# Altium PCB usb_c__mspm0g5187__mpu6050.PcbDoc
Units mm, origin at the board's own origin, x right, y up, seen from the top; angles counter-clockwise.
Board outline 64 x 33 mm, 2 copper layers (Top, Bottom), stack 0 mm thick; 29 components, 21 nets, 180 pads, 72 vias.
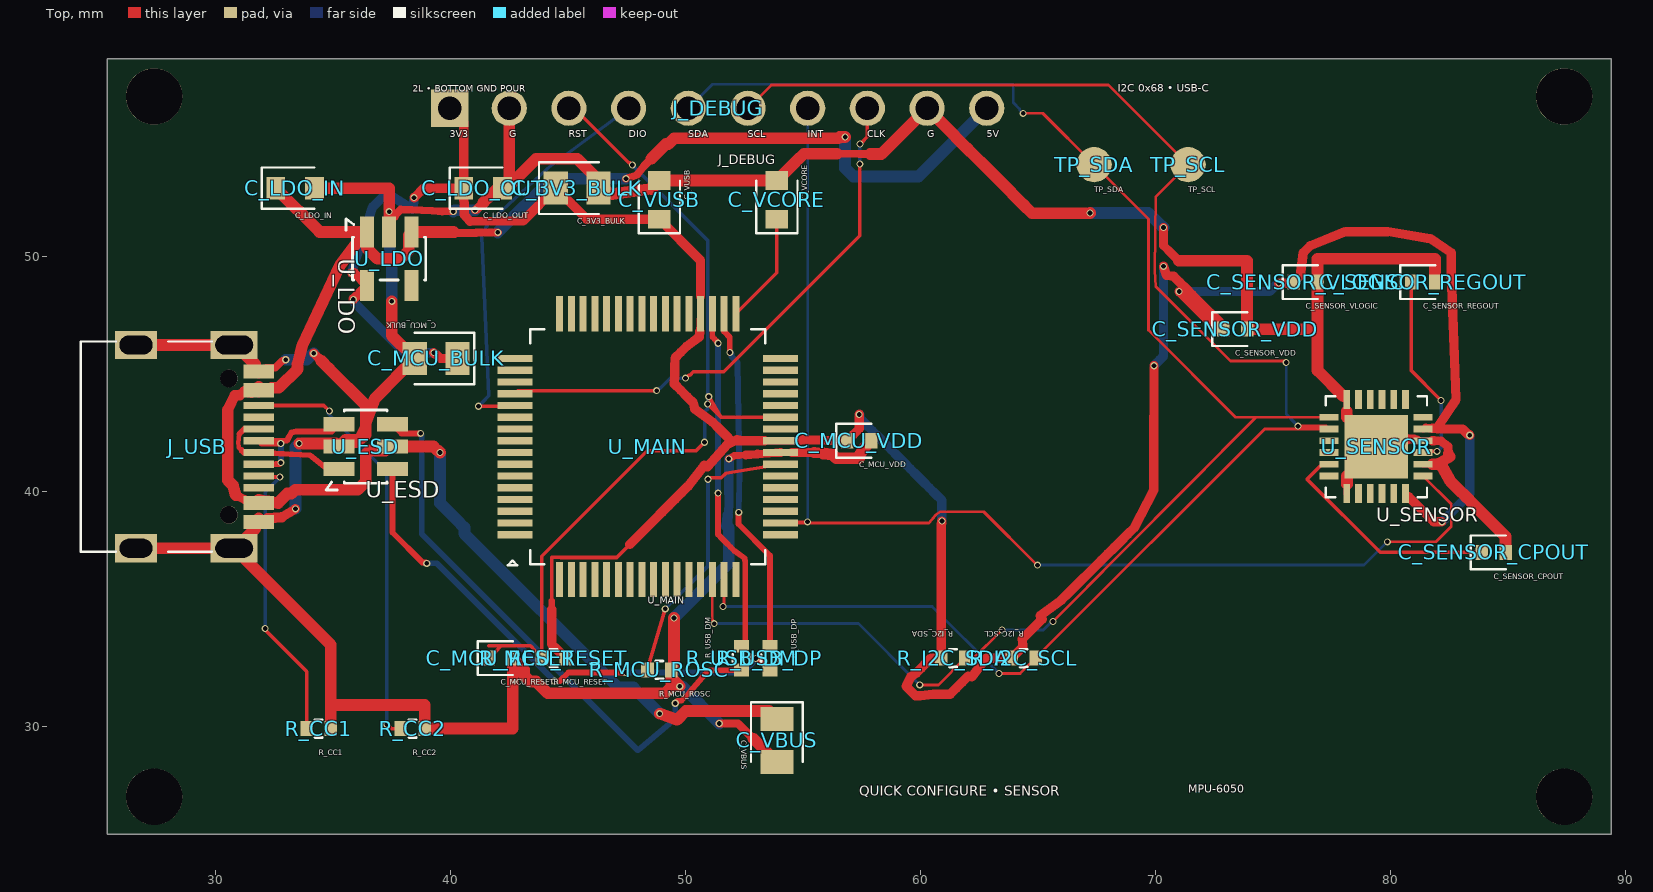
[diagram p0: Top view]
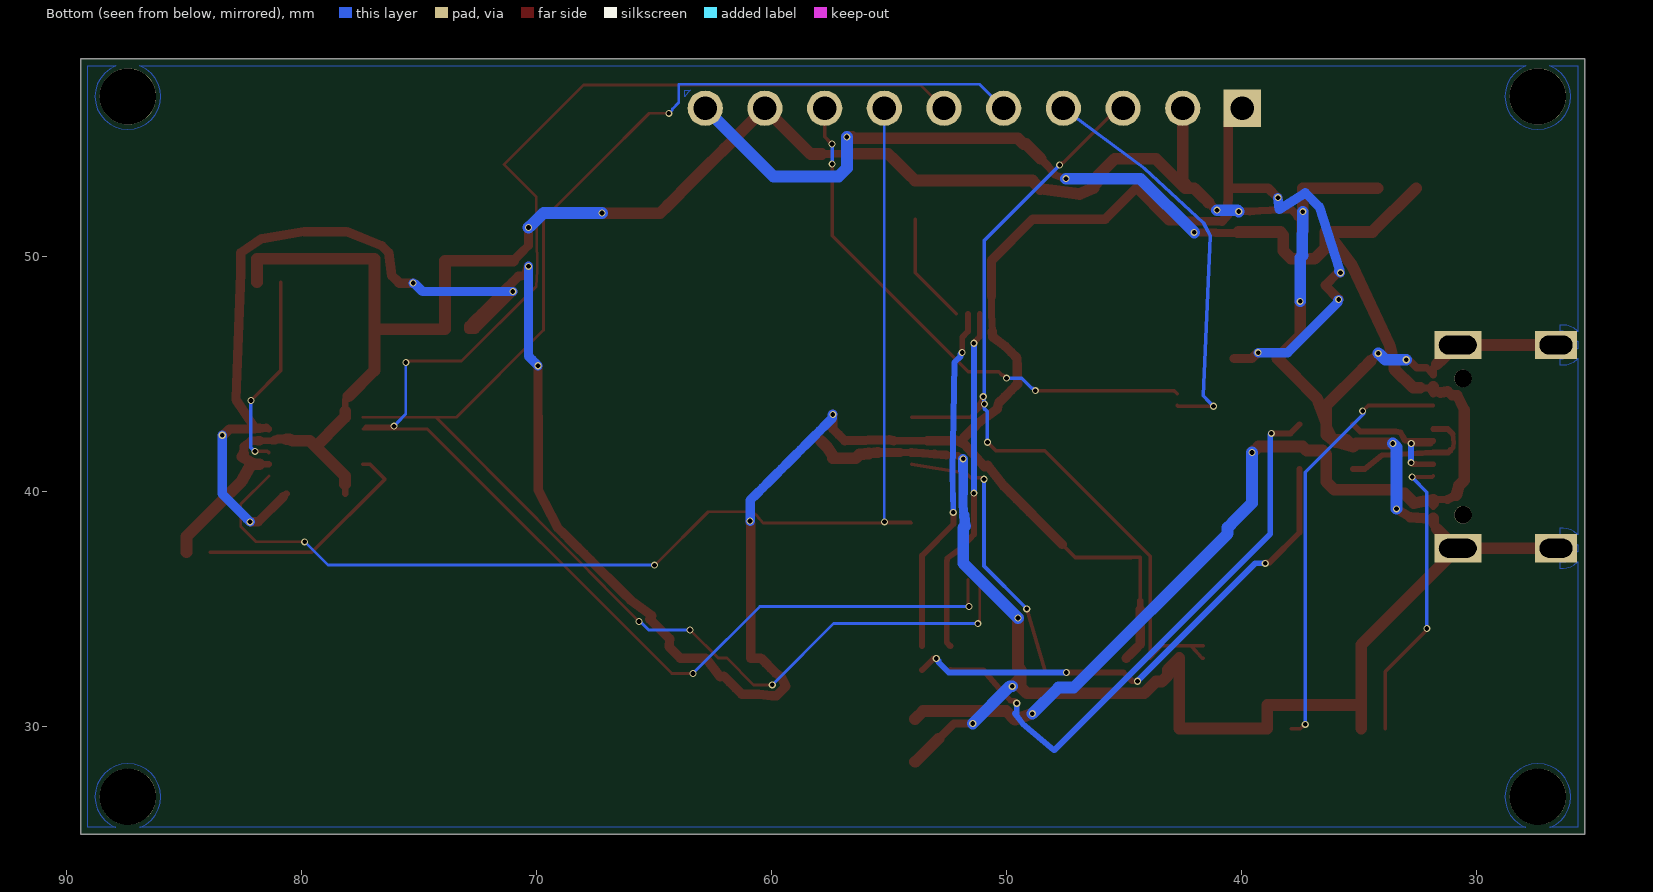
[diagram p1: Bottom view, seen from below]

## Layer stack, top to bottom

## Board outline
25.4,58.4 89.4,58.4 89.4,25.4 25.4,25.4

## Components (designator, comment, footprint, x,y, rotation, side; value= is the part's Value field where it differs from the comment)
C_3V3_BULK "" TSCIRCUIT-2.8500x1.4000mm 45.4,52.9 r0 top
C_LDO_IN "" TSCIRCUIT-2.4500x0.9500mm 33.4,52.9 r0 top
C_LDO_OUT "" TSCIRCUIT-2.4500x0.9500mm 41.4,52.9 r0 top
C_MCU_BULK "" TSCIRCUIT-2.8500x1.4000mm 39.4,45.65 r180 top
C_MCU_RESET "" TSCIRCUIT-1.5600x0.6400mm 42.15,32.9 r0 top
C_MCU_VDD "" TSCIRCUIT-1.5600x0.6400mm 57.4,42.15 r0 top
C_SENSOR_CPOUT "" TSCIRCUIT-1.5600x0.6400mm 84.4,37.4 r0 top
C_SENSOR_REGOUT "" TSCIRCUIT-1.5600x0.6400mm 81.4,48.9 r0 top
C_SENSOR_VDD "" TSCIRCUIT-1.5600x0.6400mm 73.4,46.9 r0 top
C_SENSOR_VLOGIC "" TSCIRCUIT-1.5600x0.6400mm 76.4,48.9 r0 top
C_VBUS "" TSCIRCUIT-1.4000x2.8500mm 53.9,29.4 r270 top
C_VCORE "" TSCIRCUIT-0.9500x2.4500mm 53.9,52.4 r90 top
C_VUSB "" TSCIRCUIT-0.9500x2.4500mm 48.9,52.4 r90 top
J_DEBUG "" TSCIRCUIT-24.3600x1.5000mm 51.4,56.3 r0 top
J_USB "" TSCIRCUIT-6.7732x9.8502mm 29.112,41.9 r90 top
R_CC1 "" TSCIRCUIT-1.5600x0.6400mm 34.4,29.9 r0 top
R_CC2 "" TSCIRCUIT-1.5600x0.6400mm 38.4,29.9 r0 top
R_I2C_SCL "" TSCIRCUIT-1.5600x0.6400mm 64.4,32.9 r180 top
R_I2C_SDA "" TSCIRCUIT-1.5600x0.6400mm 61.4,32.9 r180 top
R_MCU_RESET "" TSCIRCUIT-1.5600x0.6400mm 44.4,32.9 r0 top
R_MCU_ROSC "" TSCIRCUIT-1.5600x0.6400mm 48.9,32.4 r0 top
R_USB_DM "" TSCIRCUIT-0.6400x1.5600mm 52.4,32.9 r90 top
R_USB_DP "" TSCIRCUIT-0.6400x1.5600mm 53.6,32.9 r90 top
TP_SCL "" TSCIRCUIT-1.5000x1.5000mm 71.4,53.9 r0 top
TP_SDA "" TSCIRCUIT-1.5000x1.5000mm 67.4,53.9 r0 top
U_ESD "" TSCIRCUIT-3.6000x2.5000mm 36.4,41.9 r0 top
U_LDO "" TSCIRCUIT-2.5000x3.6000mm 37.4,49.9 r270 top
U_MAIN "" TSCIRCUIT-12.8000x12.8000mm 48.4,41.9 r0 top
U_SENSOR "" TSCIRCUIT-4.8000x4.8000mm 79.4,41.9 r0 top

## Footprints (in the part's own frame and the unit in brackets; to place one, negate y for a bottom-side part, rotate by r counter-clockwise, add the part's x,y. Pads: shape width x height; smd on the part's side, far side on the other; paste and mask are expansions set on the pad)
TSCIRCUIT-0.6400x1.5600mm [mm]
  rect 0.54x0.64 smd: 1(-0.51,0) 2(0.51,0)
  silkscreen extent -0.15,-0.38 0.15,0.38
TSCIRCUIT-0.9500x2.4500mm [mm]
  rect 0.8x0.95 smd: 1(-0.825,0) 2(0.825,0)
  silkscreen extent -1.42,-0.88 0.82,0.87
TSCIRCUIT-1.4000x2.8500mm [mm]
  rect 1.025x1.4 smd: 1(-0.913,0) 2(0.913,0)
  silkscreen extent -1.63,-1.1 0.91,1.1
TSCIRCUIT-1.5000x1.5000mm [mm]
  round 1.5 smd: 1(0,0)
TSCIRCUIT-1.5600x0.6400mm [mm]
  rect 0.54x0.64 smd: 1(-0.51,0) 2(0.51,0)
  silkscreen extent -0.98,-0.72 0.51,0.72
TSCIRCUIT-2.4500x0.9500mm [mm]
  rect 0.8x0.95 smd: 1(-0.825,0) 2(0.825,0)
  silkscreen extent -1.42,-0.88 0.82,0.87
TSCIRCUIT-2.5000x3.6000mm [mm]
  rect 1.325x0.6 smd: 1(-1.138,-0.95) 2(-1.138,0) 3(-1.138,0.95) 4(1.137,0.95) 5(1.137,-0.95)
  silkscreen extent -1.69,-1.84 0.91,1.56
TSCIRCUIT-2.8500x1.4000mm [mm]
  rect 1.025x1.4 smd: 1(-0.913,0) 2(0.913,0)
  silkscreen extent -1.63,-1.1 0.91,1.1
TSCIRCUIT-3.6000x2.5000mm [mm]
  rect 1.325x0.6 smd: 1(-1.138,-0.95) 2(-1.138,0) 3(-1.138,0.95) 4(1.137,0.95) 5(1.137,0) 6(1.137,-0.95)
  silkscreen extent -1.69,-1.84 0.91,1.56
TSCIRCUIT-4.8000x4.8000mm [mm]
  rect 0.28x0.8 smd: 1(-1.25,2) 2(-0.75,2) 3(-0.25,2) 4(0.25,2) 5(0.75,2) 6(1.25,2) 13(1.25,-2) 14(0.75,-2) 15(0.25,-2) 16(-0.25,-2) 17(-0.75,-2) 18(-1.242,-2)
  rect 0.8x0.28 smd: 7(2,1.25) 8(2,0.75) 9(2,0.25) 10(2,-0.25) 11(2,-0.75) 12(2,-1.25) 19(-2,-1.25) 20(-2,-0.75) 21(-2,-0.25) 22(-2,0.25) 23(-2,0.75) 24(-2,1.25)
  rect 2.7x2.7 smd: 25(0.012,0)
  silkscreen extent -2.14,-2.15 2.16,2.15
TSCIRCUIT-6.7732x9.8502mm [mm]
  rect 0.3x1.3 smd: 1(-3.35,-2.737) 2(-3.05,-2.737) 3(-2.55,-2.737) 4(-2.25,-2.737) 5(-1.75,-2.737) 6(-1.25,-2.737) 7(-0.75,-2.737) 8(-0.25,-2.737) 9(0.25,-2.737) 10(0.75,-2.737) 11(1.25,-2.737) 12(1.75,-2.737) 13(2.55,-2.737) 14(2.25,-2.737) 15(3.35,-2.737) 16(3.05,-2.737)
  rect 1.2x2 hole 0.8 slot 1.6 at 90 deg: 17(-4.325,-1.693) 18(4.325,-1.693)
  rect 1.2x1.8 hole 0.8 slot 1.4 at 90 deg: 19(4.325,2.487) 20(-4.325,2.487)
  round 0.75 hole 0.75 unplated: NPTH-1(-2.9,-1.468) NPTH-2(2.9,-1.468)
  silkscreen extent -4.47,-0.75 4.47,4.83
TSCIRCUIT-12.8000x12.8000mm [mm]
  rect 1.5x0.3 smd: 1(-5.65,-3.75) 2(-5.65,-3.25) 3(-5.65,-2.75) 4(-5.65,-2.25) 5(-5.65,-1.75) 6(-5.65,-1.25) 7(-5.65,-0.75) 8(-5.65,-0.25) 9(-5.65,0.25) 10(-5.65,0.75) 11(-5.65,1.25) 12(-5.65,1.75) 13(-5.65,2.25) 14(-5.65,2.75) 15(-5.65,3.25) 16(-5.65,3.75) 33(5.65,3.75) 34(5.65,3.25) 35(5.65,2.75) 36(5.65,2.25) 37(5.65,1.75) 38(5.65,1.25) 39(5.65,0.75) 40(5.65,0.25) 41(5.65,-0.25) 42(5.65,-0.75) 43(5.65,-1.25) 44(5.65,-1.75) 45(5.65,-2.25) 46(5.65,-2.75) 47(5.65,-3.25) 48(5.65,-3.75)
  rect 0.3x1.5 smd: 17(-3.75,5.65) 18(-3.25,5.65) 19(-2.75,5.65) 20(-2.25,5.65) 21(-1.75,5.65) 22(-1.25,5.65) 23(-0.75,5.65) 24(-0.25,5.65) 25(0.25,5.65) 26(0.75,5.65) 27(1.25,5.65) 28(1.75,5.65) 29(2.25,5.65) 30(2.75,5.65) 31(3.25,5.65) 32(3.75,5.65) 49(3.75,-5.65) 50(3.25,-5.65) 51(2.75,-5.65) 52(2.25,-5.65) 53(1.75,-5.65) 54(1.25,-5.65) 55(0.75,-5.65) 56(0.25,-5.65) 57(-0.25,-5.65) 58(-0.75,-5.65) 59(-1.25,-5.65) 60(-1.75,-5.65) 61(-2.25,-5.65) 62(-2.75,-5.65) 63(-3.25,-5.65) 64(-3.75,-5.65)
  silkscreen extent -5.95,-5.05 5,5
TSCIRCUIT-24.3600x1.5000mm [mm]
  rect 1.6x1.6 hole 1: 1(-11.43,0)
  round 1.5 hole 1: 2(-8.89,0) 3(-6.35,0) 4(-3.81,0) 5(-1.27,0) 6(1.27,0) 7(3.81,0) 8(6.35,0) 9(8.89,0) 10(11.43,0)

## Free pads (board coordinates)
  round 2.4 hole 2.4 unplated: NPTH-3(27.4,27) NPTH-4(87.4,27) NPTH-5(27.4,56.8) NPTH-6(87.4,56.8)

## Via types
v1: diameter 0.3, hole 0.2, Top to Bottom, 72 vias

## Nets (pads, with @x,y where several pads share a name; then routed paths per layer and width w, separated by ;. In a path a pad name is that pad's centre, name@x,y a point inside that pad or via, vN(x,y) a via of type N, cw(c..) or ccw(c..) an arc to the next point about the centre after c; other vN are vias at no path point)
".J_DEBUG > .pin4 to .U_MAIN > .pin12": J_DEBUG.4 U_MAIN.12 | length 17.3
  Top w0.15: v1(41.2,43.617) 42.717,43.617 U_MAIN.12
  Bottom w0.15: v1(41.2,43.617) 41.374,43.791 41.64,44.057 41.33,50.856 41.64,51.43 44.119,53.725 J_DEBUG.4
".J_DEBUG > .pin8 to .U_MAIN > .pin13": J_DEBUG.8 U_MAIN.13 | length 23
  Top w0.15: U_MAIN.13 42.88,44.28 v1(48.782,44.28) ; v1(50.011,44.814) 50.139,44.942 50.2,44.942 50.338,45.08 51.641,45.08 57.43,50.869 v1(57.43,53.93) ; v1(57.434,54.775) 57.546,54.857 57.546,54.884 57.75,55.088 J_DEBUG.8
  Bottom w0.15: v1(48.782,44.28) 48.892,44.39 48.94,44.39 49.364,44.814 v1(50.011,44.814) ; v1(57.43,53.93) 57.447,53.947 57.447,54.002 57.434,54.015 v1(57.434,54.775)
".U_MAIN > .pin42 to .R_MCU_ROSC > .pin1": R_MCU_ROSC.1 U_MAIN.42 | length 12.2
  Top w0.15: R_MCU_ROSC.1 v1(49.149,34.998) ; v1(50.968,40.512) 51.029,40.573 51.54,40.573 51.735,40.762 U_MAIN.42
  Bottom w0.15: v1(49.149,34.998) 49.177,35.026 50.968,36.817 v1(50.968,40.512)
GND: C_3V3_BULK.2 C_LDO_IN.2 C_LDO_OUT.2 C_MCU_BULK.2 C_MCU_RESET.2 C_MCU_VDD.2 C_SENSOR_CPOUT.2 C_SENSOR_REGOUT.2 C_SENSOR_VDD.2 C_SENSOR_VLOGIC.2 C_VBUS.2 C_VCORE.2 C_VUSB.2 J_DEBUG.2 J_DEBUG.9 J_USB.1 J_USB.2 J_USB.15 J_USB.16 J_USB.17 J_USB.18 J_USB.19 J_USB.20 R_CC1.2 R_CC2.2 R_MCU_ROSC.2 U_ESD.2 U_LDO.2 U_MAIN.41 U_SENSOR.1 U_SENSOR.9 U_SENSOR.11 U_SENSOR.18 U_SENSOR.25 | length 180.9
  Top w0.275: J_USB.16 J_USB.15@32.153,45.254
  Top w0.28: U_SENSOR.1@78.01,44.04 U_SENSOR.1 78.15,43.775 78.15,43.65 78.15,43.525 78.15,43.5 78.15,43.4 ; U_SENSOR.18 78.158,40.025 78.158,40.15 78.158,40.275 78.158,40.3 ; U_SENSOR.9@81,42.219 U_SENSOR.9@81.025,42.219 ; U_SENSOR.9@81.251,42.143 U_SENSOR.9 ; U_SENSOR.11 81.494,41.15 81.587,41.15 81.681,41.15 81.775,41.15 81.8,41.15 U_SENSOR.11 ; U_SENSOR.9 81.588,42.15 81.681,42.15 81.775,42.15 U_SENSOR.9@81.8,42.15
  Top w0.3: J_USB.1@31.699,38.4 J_USB.1 J_USB.1@31.849,38.7 ; 31.699,45.4 J_USB.15 J_USB.16@31.849,45.1 ; J_USB.2 31.945,38.839 32.037,38.85 32.13,38.85 J_USB.2@32.224,38.85 ; U_MAIN.41 U_MAIN.41@54.53,41.65
  Top w0.31: J_USB.16 J_USB.16@31.849,45.1
  Top w0.312: v1(51.857,41.378) 52.088,41.509 52.578,41.545
  Top w0.318: U_SENSOR.9@81.133,42.184 U_SENSOR.9@81.251,42.143
  Top w0.325: J_USB.15@32.153,45.254 32.542,45.254 32.847,45.559 v1(32.999,45.596) ; 37.883,51.98 38.356,51.98 38.791,51.955 39.226,51.931 39.661,51.907 v1(40.126,51.909) ; v1(41.055,51.962) v1@41.082,51.982 ; v1(51.447,30.117) 51.844,30.118 52.24,30.119 ; 56.46,54.36 56.929,54.358 57.398,54.355 57.868,54.353
  Top w0.35: 37.614,51.711 37.883,51.98 ; 52.24,30.119 52.572,29.793 52.904,29.467
  Top w0.375: v1@41.082,51.982 41.105,51.982 41.411,52.288 ; 52.578,41.545 53.069,41.58 53.559,41.615 U_MAIN.41 ; U_MAIN.41@54.53,41.65 55.01,41.65 55.49,41.65 ; v1(70.351,51.227) 70.351,50.843 70.351,50.459 70.675,50.135 70.998,49.812 ; 80.775,42.219 80.9,42.219 81,42.219 ; U_SENSOR.9@81.025,42.219 U_SENSOR.9@81.133,42.184 ; 81.869,42.15 81.963,42.15 82.056,42.15 82.105,42.15 82.155,42.136 82.462,41.9 82.475,41.588
  Top w0.4: 32.838,38.9 33.124,39.075 v1(33.411,39.251) ; v1(34.191,45.872) 34.516,45.547 ; U_LDO.2@37.426,51.524 37.614,51.711 ; U_SENSOR.25@80.65,42.219 80.775,42.219
  Top w0.413: 81.8,42.15 81.869,42.15
  Top w0.45: J_USB.2@32.224,38.85 32.531,38.875 32.838,38.9 ; 55.49,41.65 55.877,41.608 ; 82.013,41.15 82.044,41.181 82.3,41.322 82.556,41.463 82.475,41.588
  Top w0.5: J_USB.20 J_USB.17 ; J_USB.19 J_USB.18 ; J_USB.18 30.874,46.225 31.474,45.625 31.699,45.4 ; J_USB.1@31.699,38.4 31.474,38.175 30.874,37.575 J_USB.17 34.91,33.471 R_CC1.2 34.91,30.9 38.91,30.9 R_CC2.2 42.66,29.9 C_MCU_RESET.2 42.66,32.89 43.15,32.4 43.15,32.15 43.4,31.9 43.65,31.9 44.15,31.4 49.141,31.4 49.41,31.669 R_MCU_ROSC.2 ; J_USB.1@31.849,38.7 J_USB.2 ; v1(33.571,42.037) 35.126,42.037 U_ESD.2 ; C_LDO_IN.2 37.4,52.9 U_LDO.2 ; 34.516,45.547 34.84,45.223 36.4,43.663 36.4,42.7 36.2,42.3 36,42.1 U_ESD.2 ; v1(37.4,51.9) 37.401,51.036 U_LDO.2 ; U_LDO.2@37.426,51.524 37.426,51.064 U_LDO.2 ; v1(37.513,48.083) 37.513,46.624 C_MCU_BULK.2 38.151,45.313 37.814,44.976 37.477,44.639 37.14,44.303 36.803,43.966 36.4,42.9 36.4,42.4 36.129,42.184 35.546,42.184 U_ESD.2 ; 41.411,52.288 41.717,52.594 42.023,52.9 C_LDO_OUT.2 ; J_DEBUG.2 42.51,53.185 C_LDO_OUT.2 ; v1(49.517,34.603) 49.517,34.184 49.517,33.765 49.517,33.345 49.517,32.926 49.517,32.507 R_MCU_ROSC.2 ; v1(49.766,31.699) 49.41,32.055 R_MCU_ROSC.2 ; 52.904,29.467 53.883,28.487 C_VBUS.2 ; 55.877,41.608 56.263,41.567 56.43,41.4 57.4,41.4 57.4,41.525 57.66,41.9 C_MCU_VDD.2 ; 56.46,54.36 55.99,54.362 55.521,54.365 55.052,54.367 54.764,54.081 54.476,53.796 54.188,53.51 C_VCORE.2 C_VUSB.2 48.9,53.193 48.575,52.868 46.9,52.65 C_3V3_BULK.2 46.4,52.9 46.15,53.15 46.15,53.4 45.4,54.15 43.65,54.15 42.4,52.9 C_LDO_OUT.2 ; 57.868,54.353 58.337,54.351 58.341,54.351 J_DEBUG.9 60.634,55.956 60.977,55.613 61.321,55.269 61.664,54.926 62.008,54.582 62.351,54.239 62.695,53.895 63.038,53.552 63.382,53.208 63.725,52.865 64.069,52.521 64.412,52.178 64.756,51.834 65.242,51.834 65.729,51.834 66.216,51.834 66.703,51.834 67.19,51.834 67.219,51.834 v1(67.228,51.843) ; 70.998,49.812 73.91,49.812 C_SENSOR_VDD.2 76.91,46.9 C_SENSOR_VLOGIC.2 ; 78.01,44.04 76.91,45.14 C_SENSOR_VLOGIC.2 ; 78.15,43.4 78.15,43.275 78.15,43.162 78.159,43.154 78.247,43.065 78.336,42.977 U_SENSOR.25 ; 78.158,40.3 78.158,40.4 78.158,40.525 78.158,40.645 78.161,40.649 78.25,40.737 78.338,40.825 U_SENSOR.25 ; U_SENSOR.25@80.65,42.219 80.525,42.219 80.4,42.15 79.662,42.15 U_SENSOR.25 ; C_SENSOR_REGOUT.2 81.91,49.9 76.91,49.9 C_SENSOR_VLOGIC.2 ; 82.013,41.15 81.962,41.15 81.869,41.15 81.8,41.15 82.15,41.15 82.554,40.43 82.89,40.094 83.227,39.757 83.563,39.421 83.9,39.084 84.237,38.747 84.573,38.411 84.91,38.074 84.91,37.737 C_SENSOR_CPOUT.2
  Bottom w0.375: 51.816,38.971 51.856,39.416 51.857,39.907
  Bottom w0.4: 51.857,39.907 51.857,40.397 51.857,40.888
  Bottom w0.425: 51.857,40.888 v1(51.857,41.378)
  Bottom w0.45: 51.775,38.525 51.816,38.971
  Bottom w0.5: v1(32.999,45.596) 33.446,45.596 33.892,45.596 34.143,45.847 34.166,45.847 v1(34.191,45.872) ; v1(33.411,39.251) 33.411,41.877 v1(33.571,42.037) ; v1(37.4,51.9) 37.419,50.126 37.408,50.038 37.513,49.934 v1(37.513,48.083) ; v1(40.126,51.909) 40.18,51.962 v1(41.055,51.962) ; v1(49.517,34.603) 51.856,36.942 51.856,38.435 51.775,38.525 ; v1(49.766,31.699) 49.865,31.699 v1(51.447,30.117) ; v1(67.228,51.843) 67.723,51.843 68.218,51.843 68.713,51.843 69.208,51.843 69.703,51.843 69.976,51.57 70.25,51.296 70.282,51.296 v1(70.351,51.227)
MAIN_RESET: C_MCU_RESET.1 J_DEBUG.3 R_MCU_RESET.1 U_MAIN.38 | length 41.2
  Top w0.15: C_MCU_RESET.1 41.68,32.9 42.16,33.425 41.64,33.425 43.2,33.425 43.16,33.425 43.41,33.425 R_MCU_RESET.1 43.89,37.238 48.382,41.73 50.459,41.73 50.758,42.029 50.763,42.029 v1(50.82,42.086) ; J_DEBUG.3 45.273,56.3 47.59,53.983 47.65,53.983 v1(47.746,53.887) ; v1(50.951,43.713) 51.514,43.15 ; v1(51,44.025) 51.514,43.15 ; 51.514,43.15 U_MAIN.38 51.514,43.15
  Bottom w0.15: v1(47.746,53.887) 50.948,50.685 50.948,43.716 v1(50.951,43.713) ; v1(50.82,42.086) 50.82,43.378 50.966,43.524 50.966,43.698 v1(51,44.025)
MSP_VCORE: C_VCORE.1 U_MAIN.32 | length 4.7
  Top w0.15: U_MAIN.32 53.9,49.3 C_VCORE.1
SENSOR_CPOUT: C_SENSOR_CPOUT.1 U_SENSOR.20 | length 9.9
  Top w0.15: U_SENSOR.20 77.095,41.15 76.459,40.514 79.573,37.4 C_SENSOR_CPOUT.1
SENSOR_INT: J_DEBUG.7 U_MAIN.47 U_SENSOR.12 | length 51.9
  Top w0.12: v1(55.2,38.7) 54.1,38.7 U_MAIN.47 60.377,38.65 60.662,39 60.853,39.126 62.702,39.126 64.929,36.898 64.95,36.898 v1(64.992,36.856) ; v1(79.876,37.849) 81.941,37.849 82.601,38.508 82.601,39.45 U_SENSOR.12
  Bottom w0.12: v1(55.2,38.7) 55.198,38.698 55.124,38.698 55.21,38.784 J_DEBUG.7 ; v1(64.992,36.856) 78.883,36.856 79.841,37.814 v1(79.876,37.849)
SENSOR_REGOUT: C_SENSOR_REGOUT.1 U_SENSOR.10 | length 8.4
  Top w0.15: C_SENSOR_REGOUT.1 80.89,45.139 82.113,43.916 v1(82.165,43.864) ; U_SENSOR.10 81.464,41.706 v1(81.992,41.701)
  Bottom w0.15: v1(81.992,41.701) 82.076,41.741 82.076,41.773 82.165,41.863 v1(82.165,43.864)
SENSOR_SCL: J_DEBUG.6 R_I2C_SCL.1 TP_SCL.1 U_MAIN.50 U_SENSOR.23 | length 70
  Top w0.12: v1(51.607,35.099) 51.65,35.142 51.65,35.25 U_MAIN.50 ; J_DEBUG.6 53.663,57.293 68.007,57.293 TP_SCL.1 70.018,52.518 69.979,49.395 70.018,48.723 73.199,45.542 75.449,45.542 75.514,45.542 v1(75.573,45.483) ; v1(63.354,32.242) 64.252,32.242 R_I2C_SCL.1 74.66,42.65 U_SENSOR.23 77.278,42.772 v1(76.072,42.772)
  Bottom w0.12: v1(51.607,35.099) 60.507,35.099 63.243,32.363 63.243,32.353 v1(63.354,32.242) ; v1(75.573,45.483) 75.573,43.283 75.961,42.895 75.961,42.883 v1(76.072,42.772)
SENSOR_SDA: J_DEBUG.5 R_I2C_SDA.1 TP_SDA.1 U_MAIN.51 U_SENSOR.24 | length 70.7
  Top w0.12: U_MAIN.51 51.15,34.532 51.173,34.51 51.173,34.423 v1(51.229,34.367) ; v1(59.978,31.762) 60.772,31.762 R_I2C_SDA.1 62.276,32.9 63.431,34.055 v1(63.476,34.1) ; v1(64.379,56.084) 65.216,56.084 TP_SDA.1 69.707,51.593 69.707,46.856 73.412,43.15 U_SENSOR.24 74.286,43.15 v1(65.648,34.456)
  Bottom w0.12: J_DEBUG.5 51.153,57.323 63.956,57.323 63.956,56.54 64.231,56.265 64.231,56.232 v1(64.379,56.084) ; v1(51.229,34.367) 57.373,34.367 59.909,31.831 v1(59.978,31.762) ; v1(63.476,34.1) 65.236,34.1 65.581,34.445 v1(65.648,34.456)
usb-dm-mcu: R_USB_DM.2 U_MAIN.30 | length 14.8
  Top w0.25: U_MAIN.30 51.15,47.307 51.15,47.063 51.15,46.82 51.15,46.576 51.248,46.479 51.345,46.381 51.345,46.355 v1(51.4,46.3) ; v1(51.399,39.922) 51.399,39.701 51.399,39.481 51.399,39.26 51.399,39.039 51.399,38.819 51.399,38.598 51.399,38.377 51.399,38.157 51.574,37.982 51.748,37.807 51.923,37.632 52.098,37.458 52.525,37.15 52.556,37 52.556,36.757 52.556,36.513 52.556,36.27 52.556,36.027 52.556,35.784 52.556,35.54 52.556,35.297 52.556,35.054 52.556,34.811 52.556,34.567 52.556,34.324 52.556,34.081 52.556,33.838 52.556,33.594 52.556,33.566 R_USB_DM.2
  Bottom w0.25: v1(51.399,39.922) 51.403,39.926 51.403,40.052 51.4,40.055 51.4,40.305 51.4,40.555 51.4,40.805 51.4,41.054 51.4,41.304 51.4,41.554 51.4,41.804 51.4,42.054 51.4,42.303 51.4,42.553 51.4,42.803 51.4,43.053 51.4,43.302 51.4,43.552 51.4,43.802 51.4,44.052 51.4,44.302 51.4,44.551 51.4,44.801 51.4,45.051 51.4,45.301 51.4,45.551 51.4,45.8 51.4,46.05 v1(51.4,46.3)
usb-dm-phy: R_USB_DM.1 U_ESD.4 | length 24.9
  Top w0.25: U_ESD.4 37.922,42.466 v1(38.74,42.466) ; v1(49.574,30.98) 49.678,31.084 49.702,31.073 49.84,31.1 50.2,31.46 51,32.386 R_USB_DM.1
  Bottom w0.25: v1(38.74,42.466) 38.784,42.422 38.784,42.351 38.784,38.179 47.981,28.982 49.321,30.109 49.649,30.544 49.574,30.576 v1(49.574,30.98)
usb-dm-port: J_USB.7 J_USB.9 U_ESD.3 | length 6.5
  Top w0.25: J_USB.7 32.584,41.15 32.595,41.16 32.732,41.16 v1(32.789,41.217) ; v1(32.787,42.037) 31.965,42.034 J_USB.9 33.044,42.15 33.241,42.5 33.436,42.542 34.955,42.542 U_ESD.3
  Bottom w0.25: v1(32.787,42.037) 32.791,42.03 32.791,41.965 32.789,41.963 v1(32.789,41.217)
usb-dp-mcu: R_USB_DP.2 U_MAIN.31 | length 14.9
  Top w0.25: U_MAIN.31 U_MAIN.31 51.652,46.803 51.895,46.56 v1(51.895,45.902) ; v1(52.276,39.102) 52.264,39.063 52.264,38.607 53.6,37.271 R_USB_DP.2
  Bottom w0.25: v1(51.895,45.902) 51.962,45.835 51.962,45.742 52.229,45.478 52.307,40.802 v1(52.276,39.102)
usb-dp-phy: R_USB_DP.1 U_ESD.6 | length 22
  Top w0.25: U_ESD.6 37.537,38.245 38.807,36.976 38.959,36.976 v1(39,36.935) ; v1(44.437,31.916) 44.658,31.916 45.031,32.289 47.421,32.289 47.444,32.312 v1(47.466,32.29) ; v1(53,32.88) 53.11,32.88 R_USB_DP.1
  Bottom w0.25: v1(39,36.935) 39.423,36.935 44.426,31.932 44.426,31.927 v1(44.437,31.916) ; v1(47.466,32.29) 52.468,32.29 52.91,32.731 52.91,32.79 v1(53,32.88)
usb-dp-port: J_USB.8 J_USB.10 U_ESD.1 | length 6.1
  Top w0.188: 31.018,42.432 30.997,42.241 30.977,42.05 31.007,41.854 31.11,41.75
  Top w0.238: 31.018,42.432 31.126,42.541
  Top w0.25: 31.11,41.75 31.214,41.647 31.425,41.647 31.635,41.647 31.846,41.647 J_USB.8 34.036,41.531 34.764,40.952 35.261,40.952 U_ESD.1 ; 31.126,42.541 31.235,42.65 31.44,42.65 31.644,42.65 J_USB.10
USB_CC1: J_USB.6 R_CC1.1 | length 12.7
  Top w0.15: J_USB.6 31.892,40.607 v1(32.746,40.607) ; v1(32.121,34.156) 32.112,34.147 32.072,34.147 33.89,32.329 R_CC1.1
  Bottom w0.15: v1(32.121,34.156) 32.121,39.961 32.704,40.544 32.704,40.565 v1(32.746,40.607)
USB_CC2: J_USB.12 R_CC2.1 | length 18.2
  Top w0.15: J_USB.12 34.62,43.65 v1(34.851,43.419) ; v1(37.296,30.08) 37.394,29.982 37.424,29.982 37.506,29.9 R_CC2.1
  Bottom w0.15: v1(34.851,43.419) 34.81,43.378 34.81,43.299 37.296,40.813 v1(37.296,30.08)
VBUS5: C_LDO_IN.1 C_VBUS.1 J_DEBUG.10 J_USB.3 J_USB.4 J_USB.13 J_USB.14 U_ESD.5 U_LDO.1 U_LDO.3 | length 83.1
  Top w0.275: J_USB.3 J_USB.3@31.849,39.5
  Top w0.3: J_USB.4@31.244,39.65 31.546,39.65 J_USB.4 J_USB.3@31.849,39.5 ; J_USB.14@31.546,44.197 J_USB.14 J_USB.14@31.849,44.3 ; J_USB.13 32.1,44.4 J_USB.13@32.4,44.4
  Top w0.325: v1(47.481,53.303) 47.947,53.462 48.251,53.846
  Top w0.35: 40.181,50.99 40.642,50.997 41.103,51.003 41.564,51.01 v1(42.025,51.017) ; 48.251,53.846 48.559,54.154
  Top w0.375: 30.869,39.837 J_USB.4@31.244,39.65
  Top w0.437: 30.822,44.087 31.041,44.087 J_USB.14@31.244,44.244 ; 40.134,51.038 40.181,50.99
  Top w0.45: 30.532,43.46 30.677,43.774 30.822,44.087
  Top w0.475: J_USB.14@31.244,44.244 J_USB.14@31.546,44.197 ; J_USB.4 J_USB.4@32.265,39.572 ; J_USB.13@31.849,44.3 J_USB.13
  Top w0.5: 30.532,43.46 30.532,40.465 30.756,40.24 30.869,39.837 ; J_USB.4@32.265,39.572 32.681,39.494 32.681,39.515 33.067,39.9 33.233,39.9 33.4,40.067 36.067,40.067 36.4,40.4 36.4,41.567 36.567,41.733 37.233,41.733 37.4,41.9 U_ESD.5 37.974,41.9 38.41,41.9 38.846,41.9 39.282,41.9 39.463,41.719 39.5,41.719 v1(39.566,41.653) ; J_USB.13@32.4,44.4 32.7,44.4 33.5,45.2 33.5,45.4 33.7,46.2 35.3,49.6 36.112,50.699 U_LDO.1 ; C_LDO_IN.1 34.438,51.038 U_LDO.1 ; 40.134,51.038 U_LDO.3 38.35,51.017 38.233,50.9 38.233,50.233 37.9,49.9 36.9,49.9 36.45,50.35 U_LDO.1 ; 48.559,54.154 48.867,54.463 49.175,54.771 49.179,54.775 49.275,54.775 49.525,55.025 56.525,55.025 56.579,55.079 v1(56.803,55.079) ; v1(48.91,30.536) 49.65,30.275 50.025,30.65 52.65,30.65 53.562,30.65 C_VBUS.1
  Bottom w0.5: v1(39.566,41.653) 39.566,41.221 39.566,40.789 39.566,40.357 39.566,39.924 39.566,39.492 39.911,39.147 40.257,38.801 40.602,38.456 40.602,38.198 47.15,31.65 47.796,31.65 v1(48.91,30.536) ; v1(42.025,51.017) 44.311,53.303 v1(47.481,53.303) ; v1(56.803,55.079) 56.803,53.747 57.15,53.4 59.93,53.4 J_DEBUG.10
VCC_3V3: C_3V3_BULK.1 C_LDO_OUT.1 C_MCU_BULK.1 C_MCU_VDD.1 C_SENSOR_VDD.1 C_SENSOR_VLOGIC.1 C_VUSB.1 J_DEBUG.1 R_I2C_SCL.2 R_I2C_SDA.2 R_MCU_RESET.2 U_LDO.5 U_MAIN.29 U_MAIN.40 U_SENSOR.8 U_SENSOR.13 | length 138.7
  Top w0.15: 44.319,35.337 44.319,35.706 44.319,36.076 44.319,36.445 44.319,36.814 44.319,37.184 44.715,37.184
  Top w0.162: 44.715,37.184 45.11,37.184 45.505,37.184 45.9,37.184 46.295,37.184 46.69,37.184 47.085,37.184 47.361,37.459 47.637,37.735
  Top w0.275: 44.319,34.968 44.319,35.337
  Top w0.28: U_SENSOR.13 U_SENSOR.13@80.79,39.76 ; U_SENSOR.8@81.512,42.705 U_SENSOR.8 U_SENSOR.8@81.8,42.683
  Top w0.3: U_MAIN.29@50.612,46.8 U_MAIN.29 50.65,47.65 50.65,47.75 50.65,47.85 50.65,47.95 50.65,48.05 50.65,48.15 50.65,48.25 50.65,48.3 ; 53.3,42.15 53.65,42.15 U_MAIN.40 54.15,42.15 54.25,42.15 54.35,42.15 54.45,42.15 54.55,42.15 54.65,42.15 54.75,42.15 U_MAIN.40@54.8,42.15
  Top w0.302: U_MAIN.40@53.388,42.151 53.719,42.15 U_MAIN.40
  Top w0.368: U_SENSOR.8@81.512,42.705 U_SENSOR.8@81.8,42.673
  Top w0.4: v1(35.8,49.3) 35.912,49.3 U_LDO.5 35.876,48.188 v1(35.876,48.157) ; v1(38.46,52.494) 38.475,52.509 38.487,52.509 38.878,52.9 C_LDO_OUT.1 ; v1(39.301,45.901) 39.369,45.833 39.388,45.833 39.571,45.65 C_MCU_BULK.1 ; J_DEBUG.1 40.575,55.695 C_LDO_OUT.1 ; 44.319,34.968 44.319,34.598 44.319,34.229 44.319,33.86 44.319,33.491 44.516,33.294 44.713,33.097 R_MCU_RESET.2 ; 47.637,37.735 47.913,38.011 48.189,38.287 48.464,38.563 48.74,38.839 49.016,39.115 49.292,39.391 49.568,39.667 49.844,39.943 50.12,40.219 50.8,41.1 50.948,41.046 51.8,42 52.2,42.2 52.451,42.15 52.851,42.15 53.251,42.15 53.3,42.15 ; 50.612,46.8 50.6,46.567 50.064,46.171 49.813,45.92 49.561,45.669 49.553,45.301 49.545,44.934 49.536,44.566 49.808,44.295 50.08,44.025 50.351,43.754 50.4,43.5 51.166,42.941 51.438,42.67 51.709,42.399 51.981,42.128 52.188,42.14 52.395,42.152 52.726,42.152 53.057,42.151 U_MAIN.40@53.388,42.151 ; 50.65,48.3 50.65,48.35 50.65,49.825 C_VUSB.1 45.813,51.575 C_3V3_BULK.1 43.11,51.52 40.838,51.479 40.593,51.772 C_LDO_OUT.1 ; U_MAIN.40@54.8,42.15 55.004,42.195 C_MCU_VDD.1 57.145,42.405 57.4,42.66 57.4,42.965 v1(57.4,43.27) ; v1(60.922,38.731) 60.92,38.729 60.92,38.637 60.89,38.607 60.89,38.227 60.89,37.846 60.89,37.466 60.89,37.085 60.89,36.705 60.89,36.324 60.89,35.944 60.89,35.563 60.89,35.183 60.89,34.802 60.89,34.422 60.89,34.041 60.89,33.661 60.89,33.28 R_I2C_SDA.2 60.677,32.9 60.463,32.9 60.251,32.688 60.039,32.475 59.826,32.263 59.6,32.1 59.4,31.7 59.8,31.3 60,31.3 60.551,31.368 60.913,31.368 61.275,31.368 61.53,31.623 61.785,31.879 62.041,32.134 62.2,32.1 62.807,32.9 63.168,32.9 63.529,32.9 R_I2C_SCL.2 64.13,33.14 64.371,33.381 64.348,33.721 64.628,33.999 64.907,34.277 65.187,34.555 65.1,34.7 66.026,35.389 66.306,35.667 66.585,35.945 66.865,36.223 67.145,36.501 67.425,36.779 67.704,37.056 67.984,37.334 68.264,37.612 68.543,37.89 68.823,38.168 69.103,38.446 69.943,40.038 69.943,40.417 69.943,40.795 69.944,41.174 69.944,41.553 69.944,41.932 69.944,42.311 69.945,42.69 69.945,43.069 69.945,43.448 69.946,43.826 69.946,44.205 69.946,44.584 69.947,44.963 v1(69.947,45.342) ; v1(70.351,49.574) 70.478,49.181 70.78,49.153 71.043,48.889 71.307,48.625 71.571,48.361 71.835,48.098 72.099,47.834 72.362,47.57 72.626,47.306 72.89,47.042 C_SENSOR_VDD.1 72.62,46.9 71.043,48.477 v1(71.02,48.5) ; v1(75.259,48.86) 75.85,48.86 C_SENSOR_VLOGIC.1 76.167,49.177 76.3,50.15 76.6,50.45 78.1,51.05 79.9,51.05 81.7,50.75 82.6,50.15 82.6,49.3 82.8,43.9 82,42.7 81.8,42.683 ; U_SENSOR.13@80.79,39.76 81.85,38.7 v1(82.2,38.7) ; 81.8,42.673 82,42.65 82.1,42.65 82.2,42.65 83.074,42.65 83.305,42.42 83.349,42.42 v1(83.385,42.384)
  Bottom w0.4: v1(35.8,49.3) 35.874,49.374 35.831,49.435 36.7,52.1 37.3,52.7 38.408,51.994 v1(38.46,52.494) ; v1(35.876,48.157) 35.91,48.123 35.91,48.035 38.044,45.901 v1(39.301,45.901) ; v1(57.4,43.27) 57.421,43.249 57.421,43.114 57.69,42.845 57.96,42.576 58.229,42.307 58.498,42.037 58.768,41.768 59.037,41.499 59.306,41.229 59.575,40.96 59.845,40.691 60.114,40.421 60.383,40.152 60.653,39.883 60.922,39.614 60.922,39.319 60.922,39.025 v1(60.922,38.731) ; v1(69.947,45.342) 70.049,45.444 70.049,45.45 70.2,45.601 70.351,45.752 70.351,46.134 70.351,46.516 70.351,46.899 70.351,47.281 70.351,47.663 70.351,48.045 70.351,48.427 70.351,48.81 70.351,49.192 v1(70.351,49.574) ; v1(71.02,48.5) 74.859,48.5 75.178,48.819 75.218,48.819 v1(75.259,48.86) ; v1(82.2,38.7) 82.339,38.839 82.339,38.841 83.385,39.887 v1(83.385,42.384)
pads on no net: J_USB.5 J_USB.11 J_USB.NPTH-1 J_USB.NPTH-2 U_LDO.4 U_MAIN.1 U_MAIN.2 U_MAIN.3 U_MAIN.4 U_MAIN.5 U_MAIN.6 U_MAIN.7 U_MAIN.8 U_MAIN.9 U_MAIN.10 U_MAIN.11 U_MAIN.14 U_MAIN.15 U_MAIN.16 U_MAIN.17 U_MAIN.18 U_MAIN.19 U_MAIN.20 U_MAIN.21 U_MAIN.22 U_MAIN.23 U_MAIN.24 U_MAIN.25 U_MAIN.26 U_MAIN.27 U_MAIN.28 U_MAIN.33 U_MAIN.34 U_MAIN.35 U_MAIN.36 U_MAIN.37 U_MAIN.39 U_MAIN.43 U_MAIN.44 U_MAIN.45 U_MAIN.46 U_MAIN.48 U_MAIN.49 U_MAIN.52 U_MAIN.53 U_MAIN.54 U_MAIN.55 U_MAIN.56 U_MAIN.57 U_MAIN.58 U_MAIN.59 U_MAIN.60 U_MAIN.61 U_MAIN.62 U_MAIN.63 U_MAIN.64 U_SENSOR.2 U_SENSOR.3 U_SENSOR.4 U_SENSOR.5 U_SENSOR.6 U_SENSOR.7 U_SENSOR.14 U_SENSOR.15 U_SENSOR.16 U_SENSOR.17 U_SENSOR.19 U_SENSOR.21 U_SENSOR.22

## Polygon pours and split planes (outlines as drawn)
GND on Bottom (solid): 197 vertices, not listed, extent 25.7,25.7 89.1,58.1
GND on Bottom (solid): 63.696,57.063 63.469,57.063 63.537,57.007 63.661,56.856 63.696,56.79

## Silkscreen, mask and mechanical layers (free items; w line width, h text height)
Top Overlay:
  text "2L • BOTTOM GND POUR" at 38.4,56.9 h0.48
  text "I2C 0x68 • USB-C" at 68.4,56.9 h0.55
  text "MPU-6050" at 71.4,27.05 h0.58
  text "QUICK CONFIGURE • SENSOR" at 57.4,26.9 h0.72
